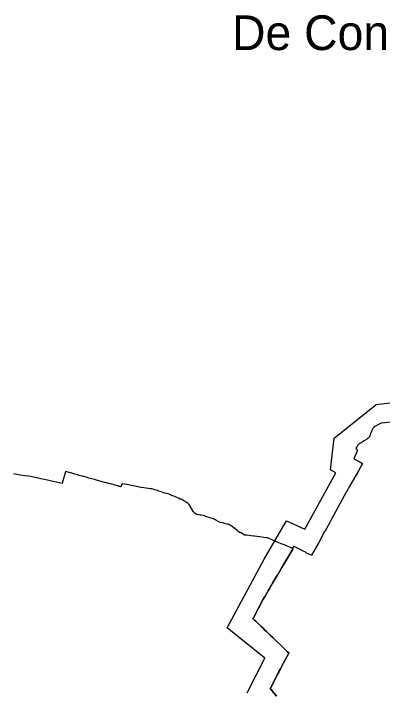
# Model space of a CAD drawing. Extents: x 113371 to 291721, y 393993 to 520143.
# Drawn here: x 186071 to 191397, y 436525 to 446286 of the extents above; entities that cross this region are included whole.
import ezdxf

# ---------------------------------------------------------------- set-up
doc = ezdxf.new("R2010")
doc.units = 0
for name, color, linetype in [('Boudingbox', 7, 'Continuous'), ('Default', 7, 'Continuous'), ('plaatsnamen', 7, 'Continuous'), ('vlieg gebied', 7, 'Continuous')]:
    doc.layers.add(name, color=color, linetype=linetype)

msp = doc.modelspace()

# ---------------------------------------------------------------- linework, layer by layer
at = {"layer": 'Boudingbox'}
msp.add_lwpolyline([(189445.661116, 436491.324097), (189698.426438, 436988.439206), (189153.109348, 437425.902392), (189691.079138, 438415.992626), (190013.242046, 438970.809739), (190274.886873, 438852.025164), (190722.392483, 439662.480076), (190645.506544, 439704.142912), (190698.109661, 440163.25452), (191307.899037, 440647.706157), (192075.170153, 440737.922), (192136.37883, 441523.814814), (192849.805815, 441867.885268), (193197.904712, 441238.347887), (194108.567653, 440545.42122), (194444.842256, 440184.882568), (194685.937826, 439741.144088), (194774.503558, 439381.668653), (195017.987247, 439384.445217), (195148.936816, 438819.576426), (195553.810692, 438228.83622), (195558.374438, 437894.219866), (195676.083719, 437658.225888), (196556.945896, 436383.18747)], dxfattribs=at)
at = {"layer": 'Default'}
for points in [[(191558.425625, 440398.7925), (191389.575625, 440381.3325), (191380.235625, 440379.3225), (191375.525625, 440378.3525), (191365.705625, 440373.8925), (191357.115625, 440369.9525), (191348.755625, 440363.9425), (191340.675625, 440358.2325), (191288.635625, 440328.8625), (191271.905625, 440319.3625), (191271.285625, 440318.9425), (191270.815625, 440318.5525), (191263.625625, 440311.4825), (191263.225625, 440311.0225), (191257.835625, 440303.0425), (191257.555625, 440302.5625), (191252.875625, 440293.8925), (191244.655625, 440275.4125), (191220.635625, 440216.9725), (191218.105625, 440205.8525), (191212.315625, 440190.4525), (191208.095625, 440183.5725), (191207.975625, 440183.3825), (191207.325625, 440182.3125), (191205.775625, 440179.7925), (191203.595625, 440176.2425), (191188.855625, 440162.2625), (191177.385625, 440153.5225), (191165.435625, 440144.8025), (191131.935625, 440122.7925), (191074.645625, 440087.8825), (191072.955625, 440086.0625), (191071.015625, 440088.7525), (191056.105625, 440078.6425), (191057.785625, 440075.1825), (191050.415625, 440071.0825)], [(191050.415625, 440071.0825), (191038.325625, 440054.8025), (191026.235625, 440038.4925), (191014.715625, 440021.8125), (191013.795625, 440020.5025), (191012.085625, 440017.7525), (191011.785625, 440017.2625), (191021.895625, 440004.2725), (191022.945625, 440003.1825), (191025.155625, 440002.8425), (191027.485625, 440002.2425), (191029.655625, 440000.3425), (191031.485625, 439998.5425), (191031.965625, 439995.8325), (191031.515625, 439991.2925), (191029.625625, 439981.9025), (191029.585625, 439981.6925), (191026.965625, 439972.5525), (191024.575625, 439965.8925), (191019.105625, 439950.8025), (191014.715625, 439940.0525), (191010.385625, 439928.2825), (191003.425625, 439912.1425), (190996.755625, 439896.1625), (190988.575625, 439874.4525), (190987.235625, 439870.8825), (190985.255625, 439865.0725), (191050.565625, 439829.6925), (191058.195625, 439825.5525), (191109.665625, 439797.6625), (191095.565625, 439772.6325), (191093.205625, 439768.4425), (191089.415625, 439761.7225), (191089.045625, 439761.0525), (191085.905625, 439755.4725), (191048.965625, 439689.8825), (190949.735625, 439518.5625), (190916.075625, 439459.3925)], [(186315.395625, 439608.2125), (186261.765625, 439617.8725), (186261.515625, 439616.9725), (186142.845625, 439635.8125), (186070.615625, 439646.9825)], [(187622.745625, 439468.5925), (187621.985625, 439466.6325), (187619.545625, 439464.0525), (187616.725625, 439463.3325), (187607.225625, 439465.7225), (187604.265625, 439466.7925), (187600.305625, 439468.2225), (187595.805625, 439469.8425), (187579.355625, 439472.2525), (187577.285625, 439473.0725), (187575.215625, 439473.6925), (187539.265625, 439484.5025), (187507.855625, 439493.3625), (187486.745625, 439499.0325), (187431.165625, 439514.2625), (187426.185625, 439515.4325), (187316.155625, 439545.1525), (187239.495625, 439566.0825), (187195.815625, 439577.8425), (187160.605625, 439588.0125), (187117.535625, 439599.8325), (187065.735625, 439614.4425), (187039.785625, 439621.3625), (187019.685625, 439626.7525), (186998.145625, 439631.8825), (186979.895625, 439637.0125), (186958.065625, 439643.1425), (186911.355625, 439656.2525), (186821.785625, 439681.4025), (186820.885625, 439678.2825), (186801.415625, 439608.9925), (186780.605625, 439533.6025), (186773.775625, 439506.8525), (186645.915625, 439537.0325), (186520.115625, 439564.9025), (186486.505625, 439572.6125), (186383.275625, 439595.2025), (186315.395625, 439608.2125)], [(188603.885625, 439207.3525), (188598.625625, 439213.3925), (188590.735625, 439220.9425), (188572.565625, 439233.3425), (188530.015625, 439259.7625), (188514.475625, 439268.8625), (188499.555625, 439278.0225), (188498.525625, 439277.0025), (188491.165625, 439280.5525), (188489.215625, 439281.2825), (188478.095625, 439285.4125), (188451.405625, 439297.5625), (188430.495625, 439305.1325), (188410.715625, 439314.5525), (188398.005625, 439319.7025), (188353.135625, 439338.2525), (188338.465625, 439344.2325), (188316.265625, 439353.3625), (188302.175625, 439358.5925), (188256.915625, 439371.7625), (188202.885625, 439388.0025), (188151.905625, 439403.2625), (188152.915625, 439406.7425), (188111.815625, 439418.4525), (188087.755625, 439425.1725), (188068.405625, 439430.7425), (188041.805625, 439434.0925), (188019.065625, 439436.7725), (187984.335625, 439440.7725), (187950.295625, 439446.4025), (187906.905625, 439453.7125), (187844.195625, 439465.8525), (187776.025625, 439479.0625), (187706.145625, 439492.8525), (187637.655625, 439506.3525), (187637.255625, 439506.0725), (187626.715625, 439478.8425), (187622.745625, 439468.5925)], [(190916.075625, 439459.3925), (190915.595625, 439458.5525), (190913.215625, 439454.3625), (190912.605625, 439453.2725), (190904.235625, 439438.5625), (190901.385625, 439433.3425), (190876.105625, 439387.0625), (190874.045625, 439383.3025), (190718.585625, 439099.9325), (190655.945625, 438983.4825), (190639.845625, 438954.6125), (190635.025625, 438946.0825), (190562.335625, 438817.6125), (190560.935625, 438815.1425), (190471.595625, 438650.8025), (190407.665625, 438535.1125), (190370.395625, 438477.9325), (190370.335625, 438477.8425), (190369.325625, 438476.2925), (190347.485625, 438485.1425), (190299.295625, 438506.7025), (190296.485625, 438510.3825), (190294.975625, 438513.2125), (190233.225625, 438544.5525), (190227.245625, 438547.8125), (190171.005625, 438575.8025), (190121.105625, 438598.4625), (190113.545625, 438601.8925), (190105.255625, 438587.2225), (190104.725625, 438586.3325), (190097.305625, 438573.8125), (190097.465625, 438573.7425), (190097.855625, 438573.5725), (190102.745625, 438571.4625), (190105.305625, 438570.3525), (190000.675625, 438392.7625), (189963.425625, 438329.5825), (189954.385625, 438313.9625)], [(189251.665625, 438869.2725), (189231.825625, 438884.5925), (189229.955625, 438886.0325), (189208.145625, 438902.8625), (189199.255625, 438907.7325), (189194.305625, 438910.4525), (189181.785625, 438916.0225), (189171.375625, 438919.9525), (189162.125625, 438922.5825), (189131.005625, 438929.3325), (189121.825625, 438931.0125), (189120.595625, 438931.2325), (189108.015625, 438934.9525), (189057.125625, 438945.9325), (189043.805625, 438951.7025), (189023.235625, 438959.6625), (188989.555625, 438980.4825), (188975.585625, 438988.3625), (188972.005625, 438990.3825), (188958.105625, 438998.6325), (188954.385625, 438999.7925), (188846.035625, 439033.2725), (188839.105625, 439036.4825), (188830.255625, 439040.5825), (188826.395625, 439042.3625), (188807.645625, 439047.4725), (188780.895625, 439051.7725), (188773.915625, 439052.1825), (188766.175625, 439052.6425), (188764.955625, 439052.8725), (188735.395625, 439058.3625), (188734.515625, 439058.5325), (188714.585625, 439062.2325), (188690.915625, 439076.7725), (188687.715625, 439079.8625), (188669.135625, 439099.2725), (188606.235625, 439203.9625), (188603.885625, 439207.3525)], [(190000.675625, 438392.7625), (190105.305625, 438570.3525), (190102.745625, 438571.4625), (190097.855625, 438573.5725), (190097.465625, 438573.7425), (190097.305625, 438573.8125), (190068.935625, 438586.0925), (190064.845625, 438587.8625), (190037.485625, 438599.7025), (190022.155625, 438606.0825), (189982.665625, 438622.5025), (189936.635625, 438640.4525), (189891.305625, 438658.1125), (189856.235625, 438672.9525), (189771.175625, 438710.6325), (189759.985625, 438715.4825), (189746.085625, 438720.9825), (189735.535625, 438724.1825), (189725.185625, 438726.1125), (189717.505625, 438727.2925), (189589.435625, 438745.3025), (189588.755625, 438745.3925), (189548.565625, 438749.9725), (189532.825625, 438751.7725), (189436.625625, 438764.4525), (189434.065625, 438764.7925), (189431.235625, 438765.1625), (189422.265625, 438762.9725), (189412.005625, 438762.3825), (189398.735625, 438770.2925), (189397.925625, 438766.7025), (189389.985625, 438772.6125), (189354.805625, 438798.7425), (189347.215625, 438804.0925), (189339.555625, 438798.2225), (189308.925625, 438824.0225), (189293.865625, 438836.7025), (189251.665625, 438869.2725)], [(189722.945625, 437374.1125), (189695.265625, 437400.3025), (189673.605625, 437421.7925), (189644.505625, 437449.3225), (189612.105625, 437480.2925), (189588.325625, 437502.7225), (189567.805625, 437522.3225), (189548.665625, 437540.3125), (189541.105625, 437547.4325), (189538.285625, 437549.9925), (189536.125625, 437551.7725), (189532.915625, 437554.2225), (189530.475625, 437555.8725), (189528.285625, 437557.2825), (189527.445625, 437557.8225), (189526.865625, 437558.1625), (189530.555625, 437565.1725), (189534.585625, 437572.8225), (189534.815625, 437573.2525), (189535.355625, 437574.2825), (189535.655625, 437574.8525), (189538.075625, 437579.4425), (189538.145625, 437579.5825), (189675.725625, 437840.6325), (189701.735625, 437884.9025), (189753.975625, 437973.0725), (189769.595625, 437999.3825), (189781.925625, 438021.5725), (189795.075625, 438043.7725), (189809.875625, 438070.0725), (189852.885625, 438141.9125), (189882.455625, 438189.8425), (189889.035625, 438200.5225), (189900.945625, 438222.3125), (189944.515625, 438296.2925), (189954.385625, 438313.9625), (189963.425625, 438329.5825), (190000.675625, 438392.7625)], [(189954.385625, 438313.9625), (189944.515625, 438296.2925), (189900.945625, 438222.3125), (189889.035625, 438200.5225), (189882.455625, 438189.8425), (189852.885625, 438141.9125), (189809.875625, 438070.0725), (189795.075625, 438043.7725), (189781.925625, 438021.5725), (189769.595625, 437999.3825), (189753.975625, 437973.0725), (189701.735625, 437884.9025), (189675.725625, 437840.6325), (189538.145625, 437579.5825), (189538.075625, 437579.4425), (189535.655625, 437574.8525), (189535.355625, 437574.2825), (189534.815625, 437573.2525), (189534.585625, 437572.8225), (189530.555625, 437565.1725), (189526.865625, 437558.1625), (189527.445625, 437557.8225), (189528.285625, 437557.2825), (189530.475625, 437555.8725), (189532.915625, 437554.2225), (189536.125625, 437551.7725), (189538.285625, 437549.9925), (189541.105625, 437547.4325), (189548.665625, 437540.3125), (189567.805625, 437522.3225), (189588.325625, 437502.7225), (189612.105625, 437480.2925), (189644.505625, 437449.3225), (189673.605625, 437421.7925), (189695.265625, 437400.3025), (189722.945625, 437374.1125), (189751.005625, 437346.6825), (189781.055625, 437318.0925)], [(189867.575625, 436441.6325), (189783.755625, 436541.7925), (189778.495625, 436548.0725), (189777.295625, 436549.5225), (189777.105625, 436549.7425), (189841.195625, 436675.8925), (189873.795625, 436742.8925), (189898.645625, 436790.7325), (189900.485625, 436794.2825), (189902.235625, 436797.6525), (189922.675625, 436837.0125), (189962.075625, 436911.8225), (190038.325625, 437054.5125), (190038.435625, 437054.7025), (190044.245625, 437065.5725), (190044.505625, 437066.0625), (190044.455625, 437066.1025), (190027.355625, 437082.4325), (189992.255625, 437116.2425), (189961.305625, 437146.1825), (189947.305625, 437159.7725), (189918.755625, 437186.7325), (189877.425625, 437225.4925), (189844.275625, 437257.7725), (189811.985625, 437288.2725), (189781.055625, 437318.0925), (189751.005625, 437346.6825), (189722.945625, 437374.1125)], [(189781.055625, 437318.0925), (189811.985625, 437288.2725), (189844.275625, 437257.7725), (189877.425625, 437225.4925), (189918.755625, 437186.7325), (189947.305625, 437159.7725), (189961.305625, 437146.1825), (189992.255625, 437116.2425), (190027.355625, 437082.4325), (190044.455625, 437066.1025), (190044.505625, 437066.0625), (190044.245625, 437065.5725), (190038.435625, 437054.7025), (190038.325625, 437054.5125), (189962.075625, 436911.8225), (189922.675625, 436837.0125), (189902.235625, 436797.6525), (189900.485625, 436794.2825), (189898.645625, 436790.7325), (189873.795625, 436742.8925), (189841.195625, 436675.8925), (189777.105625, 436549.7425), (189777.295625, 436549.5225), (189778.495625, 436548.0725), (189783.755625, 436541.7925), (189867.575625, 436441.6325)]]:
    msp.add_lwpolyline(points, dxfattribs=at)
at = {"layer": 'vlieg gebied'}
msp.add_lwpolyline([(189445.661116, 436491.324097), (189698.426438, 436988.439206), (189153.109348, 437425.902392), (189691.079138, 438415.992626), (190013.242046, 438970.809739), (190274.886873, 438852.025164), (190722.392483, 439662.480076), (190645.506544, 439704.142912), (190698.109661, 440163.25452), (191307.899037, 440647.706157), (192075.170153, 440737.922), (192136.37883, 441523.814814), (192849.805815, 441867.885268), (193197.904712, 441238.347887), (194108.567653, 440545.42122), (194444.842256, 440184.882568), (194685.937826, 439741.144088), (194774.503558, 439381.668653), (195017.987247, 439384.445217), (195148.936816, 438819.576426), (195553.810692, 438228.83622), (195558.374438, 437894.219866), (195676.083719, 437658.225888), (196556.945896, 436383.18747)], dxfattribs=at)

# ---------------------------------------------------------------- texts
at = {"layer": 'plaatsnamen'}
msp.add_text('De Connectie', height=500, dxfattribs=at).set_placement((189225.308913, 445759.207772))

doc.saveas('drawing.dxf')
